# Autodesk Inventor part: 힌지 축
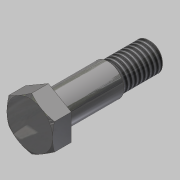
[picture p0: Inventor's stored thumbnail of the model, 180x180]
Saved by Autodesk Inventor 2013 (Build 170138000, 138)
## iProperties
Created: 2019-09
Part Number: 힌지 축
Material: 스테인리스강
Document SubType Name: Modeling
Designer: mduedu
Density: 8.08 g/cm^3
Mass: 19.8099 g
Surface Area: 13.175 cm^2
Volume: 2.45172 cm^3
Author: mduedu
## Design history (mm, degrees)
sketch "스케치1"
  geometry: C1 r 4 at (0, 0); 1 further point
  constraints: 1 centre point, 1 coincident
  dimensions: "d0" = 8 diameter of C1
extrude "돌출1" new body sketch "스케치1" distance "d1" = 29; taper "d2" = 0 deg
sketch "스케치2"
  geometry: C1 r 4.5 at (0, 0); 1 further point
  constraints: 1 centre point, 1 coincident
  dimensions: "d3" = 9 diameter of C1
extrude "돌출2" join sketch "스케치2" distance "d4" = 17.5; taper "d5" = 0 deg
sketch "스케치3"
  geometry: L1 (0, 7.506)-(6.5, 3.753); L2 (6.5, 3.753)-(6.5, -3.753); L3 (6.5, -3.753)-(0, -7.506); L4 (0, -7.506)-(-6.5, -3.753); L5 (-6.5, -3.753)-(-6.5, 3.753); L6 (-6.5, 3.753)-(0, 7.506); C1 r 6.5 at (0, 0); 2 further points
  constraints: 12 end point, 2 coincident, 1 centre point, 1 tangent, 1 vertical alignment, 13 other
  dimensions: "d6" = 6.5 radius of C1
extrude "돌출3" join sketch "스케치3" distance "d8" = 5.3; taper "d9" = 0 deg
sketch "스케치4"
  geometry: L1 (-4, 11.5)-(-4.5, 11.5) reference; L2 (-4.5, 11.5)-(-4.5, 29) reference; L3 (-4.5, 29)-(-7.506, 29) reference; L4 (-7.506, 29)-(-7.506, 34.3) reference; L5 (-7.506, 34.3)-(7.506, 34.3) reference; L6 (7.506, 34.3)-(7.506, 29) reference; L7 (7.506, 29)-(4.5, 29) reference; L8 (4.5, 29)-(4.5, 11.5) reference; L9 (4.5, 11.5)-(4, 11.5) reference; L10 (4, 11.5)-(4, 0) reference; L11 (4, 0)-(-4, 0) reference; L12 (-4, 0)-(-4, 11.5) reference; L13 (0, 0)-(0, 34.3); L14 (7.506, 34.3)-(7.506, 33.746); L15 (6.506, 34.3)-(7.506, 33.746); L16 (7.506, 34.3)-(6.506, 34.3); L17 (4.5, 29)-(4, 29); L18 (4, 29)-(4, 28.5); L19 (4, 28.5)-(4.5, 28.5); L20 (4.5, 28.5)-(4.5, 29)
  constraints: 16 end point, 2 parallel, 2 perpendicular, 2 point on line, 1 horizontal, 1 midpoint
  dimensions: "d10" = 1 distance of L5.end L15.start; "d11" = 29 deg angle of L15 L5; "d12" = 0.5 distance of L19.end L7.end; "d13" = 0.5 distance of L18.end L19.end
revolve "회전1" sketch "스케치4" stored, may be unused: angle "d14" = 90 deg
feature "스레드1" dims "d15" = 10, "d16" = 0
chamfer "모따기1" distance "d17" = 0.5; stored, may be unused: second distance "d18" = 2, angle "d19" = 45 deg
chamfer "모따기2" distance "d20" = 0.5; stored, may be unused: second distance "d21" = 2, angle "d22" = 45 deg
node "솔리드1"
node "절단 모서리 투영1"
